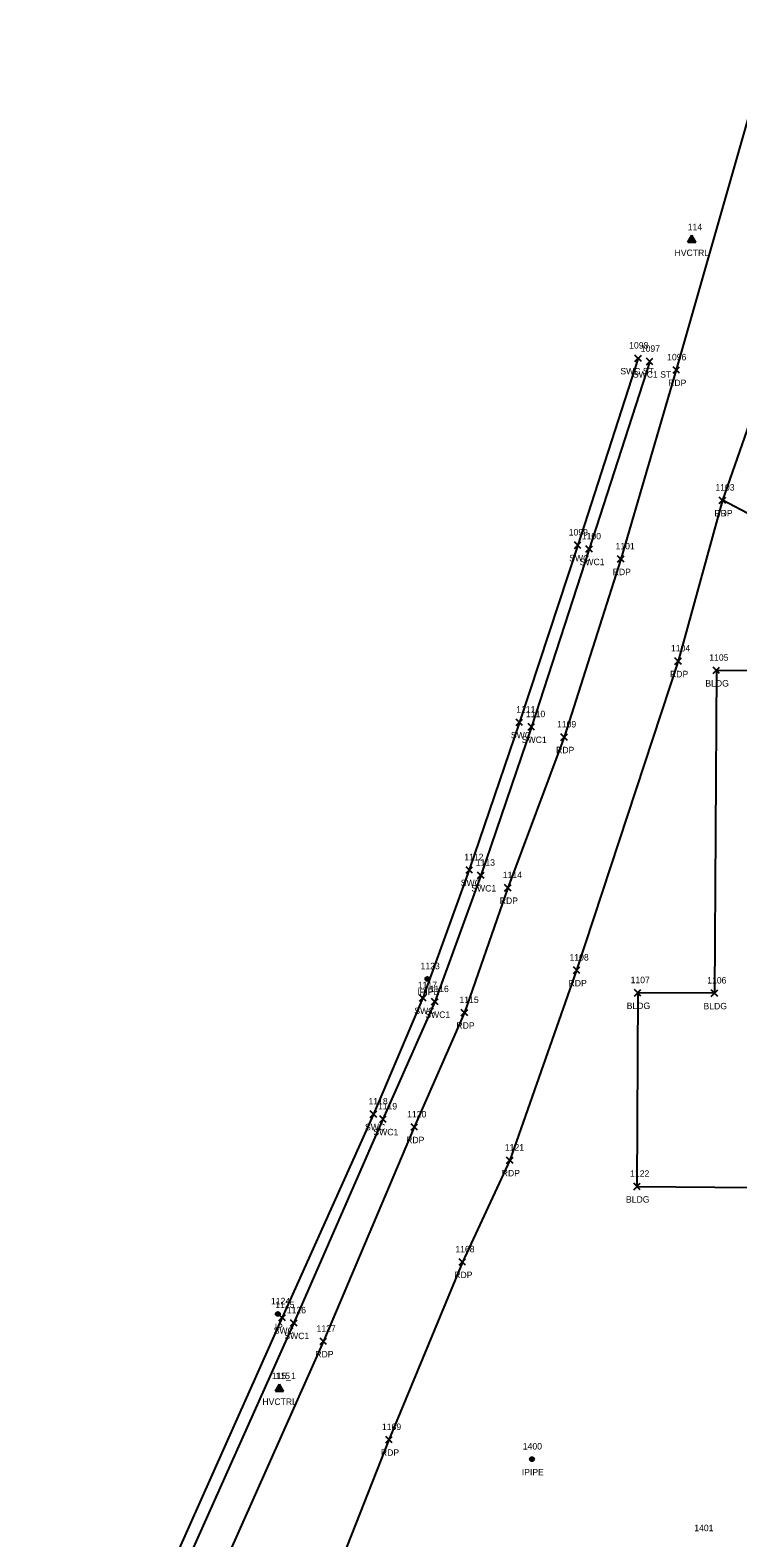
# Model space of a CAD drawing. Extents: x 1767353 to 1772625, y 740790 to 747702.
# Drawn here: x 1770036.3 to 1770255.6, y 742669.5 to 743136.9 of the extents above; entities that cross this region are included whole.
import ezdxf

# ---------------------------------------------------------------- set-up
doc = ezdxf.new("R2010")
doc.units = 0
for name, color, linetype in [('C_A', 7, 'Continuous'), ('C_I', 7, 'Continuous'), ('CPSM', 7, 'Continuous'), ('L_A', 7, 'Continuous'), ('L_I', 7, 'Continuous'), ('L_TIC', 7, 'Continuous'), ('LBC', 7, 'Continuous'), ('M_A', 7, 'Continuous'), ('M_I', 7, 'Continuous'), ('MPIP', 7, 'Continuous'), ('MPIR', 7, 'Continuous'), ('P_A', 7, 'Continuous'), ('P_I', 7, 'Continuous'), ('P_TIC', 7, 'Continuous'), ('PET', 7, 'Continuous'), ('R_A', 7, 'Continuous'), ('R_I', 7, 'Continuous'), ('R_TIC', 7, 'Continuous'), ('RDP', 7, 'Continuous'), ('RSW', 7, 'Continuous')]:
    doc.layers.add(name, color=color, linetype=linetype)

msp = doc.modelspace()

# ---------------------------------------------------------------- linework, layer by layer
at = {"layer": 'CPSM'}
for p, q in [((1770240.05, 743071.17), (1770241.3, 743073.33)), ((1770240.05, 743071.17), (1770241.3, 743073.33)), ((1770240.05, 743071.17), (1770241.3, 743073.33)), ((1770240.05, 743071.17), (1770241.3, 743073.33)), ((1770240.05, 743071.17), (1770241.3, 743073.33)), ((1770240.05, 743071.17), (1770241.3, 743073.33)), ((1770240.05, 743071.17), (1770241.3, 743073.33)), ((1770240.05, 743071.17), (1770241.3, 743071.89)), ((1770240.05, 743071.17), (1770241.3, 743071.89)), ((1770240.05, 743071.17), (1770241.3, 743071.89)), ((1770240.05, 743071.17), (1770241.3, 743071.89)), ((1770240.05, 743071.17), (1770241.3, 743071.89)), ((1770240.05, 743071.17), (1770241.3, 743071.89)), ((1770240.05, 743071.17), (1770241.3, 743071.89)), ((1770242.55, 743071.17), (1770241.3, 743073.33)), ((1770241.3, 743071.89), (1770241.3, 743073.33)), ((1770242.55, 743071.17), (1770241.3, 743073.33)), ((1770241.3, 743071.89), (1770241.3, 743073.33)), ((1770242.55, 743071.17), (1770241.3, 743073.33)), ((1770241.3, 743071.89), (1770241.3, 743073.33)), ((1770242.55, 743071.17), (1770241.3, 743073.33)), ((1770241.3, 743071.89), (1770241.3, 743073.33)), ((1770242.55, 743071.17), (1770241.3, 743073.33)), ((1770241.3, 743071.89), (1770241.3, 743073.33)), ((1770242.55, 743071.17), (1770241.3, 743073.33)), ((1770241.3, 743071.89), (1770241.3, 743073.33)), ((1770242.55, 743071.17), (1770241.3, 743073.33)), ((1770241.3, 743071.89), (1770241.3, 743073.33)), ((1770241.3, 743071.89), (1770241.3, 743071.89)), ((1770241.3, 743071.89), (1770242.55, 743071.17)), ((1770241.3, 743071.89), (1770241.3, 743071.89)), ((1770241.3, 743071.89), (1770242.55, 743071.17)), ((1770241.3, 743071.89), (1770241.3, 743071.89)), ((1770241.3, 743071.89), (1770242.55, 743071.17)), ((1770241.3, 743071.89), (1770241.3, 743071.89)), ((1770241.3, 743071.89), (1770242.55, 743071.17)), ((1770241.3, 743071.89), (1770241.3, 743071.89)), ((1770241.3, 743071.89), (1770242.55, 743071.17)), ((1770241.3, 743071.89), (1770241.3, 743071.89)), ((1770241.3, 743071.89), (1770242.55, 743071.17)), ((1770241.3, 743071.89), (1770241.3, 743071.89)), ((1770241.3, 743071.89), (1770242.55, 743071.17)), ((1770240.05, 743071.17), (1770242.55, 743071.17)), ((1770240.05, 743071.17), (1770242.55, 743071.17)), ((1770240.05, 743071.17), (1770242.55, 743071.17)), ((1770240.05, 743071.17), (1770242.55, 743071.17)), ((1770240.05, 743071.17), (1770242.55, 743071.17)), ((1770240.05, 743071.17), (1770242.55, 743071.17)), ((1770240.05, 743071.17), (1770242.55, 743071.17)), ((1770112.3, 742715), (1770113.55, 742717.17)), ((1770112.3, 742715), (1770113.55, 742717.17)), ((1770112.3, 742715), (1770113.55, 742717.17)), ((1770112.3, 742715), (1770113.55, 742717.17)), ((1770112.3, 742715), (1770113.55, 742717.17)), ((1770112.3, 742715), (1770113.55, 742717.17)), ((1770112.3, 742715), (1770113.55, 742717.17)), ((1770114.8, 742715), (1770113.55, 742717.17)), ((1770113.55, 742715.72), (1770113.55, 742717.17)), ((1770114.8, 742715), (1770113.55, 742717.17)), ((1770113.55, 742715.72), (1770113.55, 742717.17)), ((1770114.8, 742715), (1770113.55, 742717.17)), ((1770113.55, 742715.72), (1770113.55, 742717.17)), ((1770114.8, 742715), (1770113.55, 742717.17)), ((1770113.55, 742715.72), (1770113.55, 742717.17)), ((1770114.8, 742715), (1770113.55, 742717.17)), ((1770113.55, 742715.72), (1770113.55, 742717.17)), ((1770114.8, 742715), (1770113.55, 742717.17)), ((1770113.55, 742715.72), (1770113.55, 742717.17)), ((1770114.8, 742715), (1770113.55, 742717.17)), ((1770113.55, 742715.72), (1770113.55, 742717.17)), ((1770112.3, 742715), (1770113.55, 742715.72)), ((1770112.3, 742715), (1770113.55, 742715.72)), ((1770112.3, 742715), (1770113.55, 742715.72)), ((1770112.3, 742715), (1770113.55, 742715.72)), ((1770112.3, 742715), (1770113.55, 742715.72)), ((1770112.3, 742715), (1770113.55, 742715.72)), ((1770112.3, 742715), (1770113.55, 742715.72)), ((1770112.3, 742715), (1770114.8, 742715)), ((1770112.3, 742715), (1770114.8, 742715)), ((1770112.3, 742715), (1770114.8, 742715)), ((1770112.3, 742715), (1770114.8, 742715)), ((1770112.3, 742715), (1770114.8, 742715)), ((1770112.3, 742715), (1770114.8, 742715)), ((1770112.3, 742715), (1770114.8, 742715)), ((1770113.55, 742715.72), (1770113.55, 742715.72)), ((1770113.55, 742715.72), (1770114.8, 742715)), ((1770113.55, 742715.72), (1770113.55, 742715.72)), ((1770113.55, 742715.72), (1770114.8, 742715)), ((1770113.55, 742715.72), (1770113.55, 742715.72)), ((1770113.55, 742715.72), (1770114.8, 742715)), ((1770113.55, 742715.72), (1770113.55, 742715.72)), ((1770113.55, 742715.72), (1770114.8, 742715)), ((1770113.55, 742715.72), (1770113.55, 742715.72)), ((1770113.55, 742715.72), (1770114.8, 742715)), ((1770113.55, 742715.72), (1770113.55, 742715.72)), ((1770113.55, 742715.72), (1770114.8, 742715)), ((1770113.55, 742715.72), (1770113.55, 742715.72)), ((1770113.55, 742715.72), (1770114.8, 742715))]:
    msp.add_line(p, q, dxfattribs=at)
at = {"layer": 'L_TIC'}
for points in [[(1770247.94, 742937.42), (1770249.94, 742939.42)], [(1770249.94, 742937.42), (1770247.94, 742939.42)], [(1770223.56, 742837.46), (1770225.56, 742839.46)], [(1770225.56, 742837.46), (1770223.56, 742839.46)], [(1770247.37, 742837.36), (1770249.37, 742839.36)], [(1770249.37, 742837.36), (1770247.37, 742839.36)], [(1770223.34, 742777.43), (1770225.34, 742779.43)], [(1770225.34, 742777.43), (1770223.34, 742779.43)]]:
    msp.add_lwpolyline(points, dxfattribs=at)
at = {"layer": 'LBC'}
for points in [[(1770248.94, 742938.42), (1770248.37, 742838.36), (1770224.56, 742838.46), (1770224.34, 742778.43)], [(1770309.49, 742938.27), (1770248.94, 742938.42)], [(1770224.34, 742778.43), (1770308.79, 742777.69)]]:
    msp.add_lwpolyline(points, dxfattribs=at)
at = {"layer": 'MPIP'}
for centre, radius in [((1770159.38, 742842.79), 0.625), ((1770159.38, 742842.79), 0.0833), ((1770191.8, 742693.89), 0.625), ((1770191.8, 742693.89), 0.0833)]:
    msp.add_circle(centre, radius, dxfattribs=at)
at = {"layer": 'MPIR'}
for radius in [0.625, 0.0833]:
    msp.add_circle((1770113.02, 742738.91), radius, dxfattribs=at)
at = {"layer": 'P_TIC'}
for points in [[(1770235.51, 743030.56), (1770237.51, 743032.56)], [(1770237.51, 743030.56), (1770235.51, 743032.56)], [(1770249.85, 742990.18), (1770251.85, 742992.18)], [(1770251.85, 742990.18), (1770249.85, 742992.18)], [(1770218.34, 742971.95), (1770220.34, 742973.95)], [(1770220.34, 742971.95), (1770218.34, 742973.95)], [(1770236.09, 742940.3), (1770238.09, 742942.3)], [(1770238.09, 742940.3), (1770236.09, 742942.3)], [(1770200.78, 742916.74), (1770202.78, 742918.74)], [(1770202.78, 742916.74), (1770200.78, 742918.74)], [(1770183.32, 742870.03), (1770185.32, 742872.03)], [(1770185.32, 742870.03), (1770183.32, 742872.03)], [(1770204.64, 742844.48), (1770206.64, 742846.48)], [(1770206.64, 742844.48), (1770204.64, 742846.48)], [(1770169.89, 742831.33), (1770171.89, 742833.33)], [(1770171.89, 742831.33), (1770169.89, 742833.33)], [(1770154.31, 742795.84), (1770156.31, 742797.84)], [(1770156.31, 742795.84), (1770154.31, 742797.84)], [(1770183.95, 742785.57), (1770185.95, 742787.57)], [(1770185.95, 742785.57), (1770183.95, 742787.57)], [(1770169.21, 742754.02), (1770171.21, 742756.02)], [(1770171.21, 742754.02), (1770169.21, 742756.02)], [(1770126.15, 742729.43), (1770128.15, 742731.43)], [(1770128.15, 742729.43), (1770126.15, 742731.43)], [(1770146.48, 742698.94), (1770148.48, 742700.94)], [(1770148.48, 742698.94), (1770146.48, 742700.94)]]:
    msp.add_lwpolyline(points, dxfattribs=at)
at = {"layer": 'PET'}
for points in [[(1770287.36, 743218.01), (1770265.05, 743131.43), (1770236.51, 743031.56), (1770219.34, 742972.95), (1770201.78, 742917.74), (1770184.32, 742871.03), (1770170.89, 742832.33), (1770155.31, 742796.84), (1770127.15, 742730.43), (1770071.7, 742605.94), (1770068.18, 742600.07), (1770059.84, 742596.32), (1770058.18, 742592.27), (1770056.9, 742590.58), (1770055.34, 742589.72), (1770052.72, 742590.21), (1770049.12, 742591.83), (1770036.26, 742597.45)], [(1770318.5, 743207.69), (1770296.17, 743121.09), (1770250.85, 742991.18), (1770237.09, 742941.3), (1770205.64, 742845.48), (1770184.95, 742786.57), (1770170.21, 742755.02), (1770147.48, 742699.94), (1770126.77, 742647.43)]]:
    msp.add_lwpolyline(points, dxfattribs=at)
at = {"layer": 'R_TIC'}
for points in [[(1770223.69, 743034.2), (1770225.69, 743036.2)], [(1770225.69, 743034.2), (1770223.69, 743036.2)], [(1770227.29, 743033.19), (1770229.29, 743035.19)], [(1770229.29, 743033.19), (1770227.29, 743035.19)], [(1770249.85, 742990.18), (1770251.85, 742992.18)], [(1770251.85, 742990.18), (1770249.85, 742992.18)], [(1770204.97, 742976.24), (1770206.97, 742978.24)], [(1770206.97, 742976.24), (1770204.97, 742978.24)], [(1770208.52, 742975.05), (1770210.52, 742977.05)], [(1770210.52, 742975.05), (1770208.52, 742977.05)], [(1770186.9, 742921.34), (1770188.9, 742923.34)], [(1770188.9, 742921.34), (1770186.9, 742923.34)], [(1770190.6, 742919.92), (1770192.6, 742921.92)], [(1770192.6, 742919.92), (1770190.6, 742921.92)], [(1770171.36, 742875.56), (1770173.36, 742877.56)], [(1770173.36, 742875.56), (1770171.36, 742877.56)], [(1770174.94, 742873.88), (1770176.94, 742875.88)], [(1770176.94, 742873.88), (1770174.94, 742875.88)], [(1770156.95, 742835.89), (1770158.95, 742837.89)], [(1770158.95, 742835.89), (1770156.95, 742837.89)], [(1770160.68, 742834.7), (1770162.68, 742836.7)], [(1770162.68, 742834.7), (1770160.68, 742836.7)], [(1770141.69, 742799.86), (1770143.69, 742801.86)], [(1770143.69, 742799.86), (1770141.69, 742801.86)], [(1770144.6, 742798.3), (1770146.6, 742800.3)], [(1770146.6, 742798.3), (1770144.6, 742800.3)], [(1770113.37, 742736.77), (1770115.37, 742738.77)], [(1770115.37, 742736.77), (1770113.37, 742738.77)], [(1770116.99, 742735.11), (1770118.99, 742737.11)], [(1770118.99, 742735.11), (1770116.99, 742737.11)]]:
    msp.add_lwpolyline(points, dxfattribs=at)
at = {"layer": 'RDP'}
msp.add_lwpolyline([(1770358.02, 742818.47), (1770383, 742815.07), (1770381.79, 742805.76), (1770402.35, 742803.35), (1770416, 742845.87), (1770417.24, 742925.38), (1770417.05, 742964.46), (1770339.87, 742963.82), (1770324.43, 742957.55), (1770311.28, 742959.37), (1770250.85, 742991.18)], dxfattribs=at)
at = {"layer": 'RSW'}
for points in [[(1770224.69, 743035.2), (1770205.97, 742977.24), (1770187.9, 742922.34), (1770172.36, 742876.56), (1770157.95, 742836.89), (1770142.69, 742800.86), (1770114.37, 742737.77), (1770052.67, 742599.45), (1770040.21, 742604.87)], [(1770228.29, 743034.19), (1770209.52, 742976.05), (1770191.6, 742920.92), (1770175.94, 742874.88), (1770161.68, 742835.7), (1770145.6, 742799.3), (1770117.99, 742736.11), (1770056.07, 742597.76), (1770059.84, 742596.32)]]:
    msp.add_lwpolyline(points, dxfattribs=at)

# ---------------------------------------------------------------- texts
at = {"layer": 'C_A'}
for p in [(1770235.99, 743066.89), (1770235.99, 743066.89), (1770235.99, 743066.89), (1770235.99, 743066.89), (1770235.99, 743066.89), (1770235.99, 743066.89), (1770235.99, 743066.89), (1770108.24, 742710.72), (1770108.24, 742710.72), (1770108.24, 742710.72), (1770108.24, 742710.72), (1770108.24, 742710.72), (1770108.24, 742710.72), (1770108.24, 742710.72)]:
    msp.add_text('HVCTRL', height=2, dxfattribs=at).set_placement(p)
at = {"layer": 'C_I'}
for s, p in [('114', (1770240.07, 743074.89)), ('114', (1770240.07, 743074.89)), ('114', (1770240.07, 743074.89)), ('114', (1770240.07, 743074.89)), ('114', (1770240.07, 743074.89)), ('114', (1770240.07, 743074.89)), ('114', (1770240.07, 743074.89)), ('115_1', (1770111.17, 742718.72)), ('115', (1770112.32, 742718.72)), ('115', (1770112.32, 742718.72)), ('115', (1770112.32, 742718.72)), ('115', (1770112.32, 742718.72)), ('115', (1770112.32, 742718.72)), ('115', (1770112.32, 742718.72))]:
    msp.add_text(s, height=2, dxfattribs=at).set_placement(p)
at = {"layer": 'L_A'}
for p in [(1770245.53, 742933.42), (1770221.15, 742833.46), (1770244.96, 742833.36), (1770220.93, 742773.43)]:
    msp.add_text('BLDG', height=2, dxfattribs=at).set_placement(p)
at = {"layer": 'L_I'}
for s, p in [('1105', (1770246.74, 742941.42)), ('1107', (1770222.36, 742841.46)), ('1106', (1770246.11, 742841.36)), ('1122', (1770222.21, 742781.43))]:
    msp.add_text(s, height=2, dxfattribs=at).set_placement(p)
at = {"layer": 'M_A'}
for s, p in [('IPIPE', (1770156.22, 742837.79)), ('IP', (1770112.07, 742733.91)), ('IPIPE', (1770188.64, 742688.89))]:
    msp.add_text(s, height=2, dxfattribs=at).set_placement(p)
at = {"layer": 'M_I'}
for s, p in [('1123', (1770157.26, 742845.79)), ('1124', (1770110.9, 742741.91)), ('1400', (1770188.95, 742696.89)), ('1401', (1770242.09, 742671.57))]:
    msp.add_text(s, height=2, dxfattribs=at).set_placement(p)
at = {"layer": 'P_A'}
for p in [(1770234, 743026.56), (1770248.33, 742986.18), (1770216.82, 742967.95), (1770234.58, 742936.3), (1770199.27, 742912.74), (1770181.81, 742866.03), (1770203.13, 742840.48), (1770168.38, 742827.33), (1770152.8, 742791.84), (1770182.43, 742781.57), (1770167.7, 742750.02), (1770124.64, 742725.43), (1770144.97, 742694.94)]:
    msp.add_text('RDP', height=2, dxfattribs=at).set_placement(p)
at = {"layer": 'P_I'}
for s, p in [('1096', (1770233.68, 743034.56)), ('1103', (1770248.64, 742994.18)), ('1101', (1770217.7, 742975.95)), ('1104', (1770234.88, 742944.3)), ('1109', (1770199.56, 742920.74)), ('1114', (1770182.76, 742874.03)), ('1108', (1770203.43, 742848.48)), ('1115', (1770169.33, 742835.33)), ('1120', (1770153.1, 742799.84)), ('1121', (1770183.39, 742789.57)), ('1168', (1770168.04, 742758.02)), ('1127', (1770125.03, 742733.43)), ('1169', (1770145.3, 742702.94))]:
    msp.add_text(s, height=2, dxfattribs=at).set_placement(p)
at = {"layer": 'R_A'}
for s, p in [('SWC ST', (1770219.19, 743030.2)), ('SWC1 ST', (1770223.07, 743029.19)), ('DRP', (1770248.33, 742986.18)), ('SWC', (1770203.33, 742972.24)), ('SWC1', (1770206.56, 742971.05)), ('SWC', (1770185.26, 742917.34)), ('SWC1', (1770188.64, 742915.92)), ('SWC', (1770169.72, 742871.56)), ('SWC1', (1770172.98, 742869.88)), ('SWC', (1770155.32, 742831.89)), ('SWC1', (1770158.72, 742830.7)), ('SWC', (1770140.05, 742795.86)), ('SWC1', (1770142.64, 742794.3)), ('SWC', (1770111.73, 742732.77)), ('SWC1', (1770115.03, 742731.11))]:
    msp.add_text(s, height=2, dxfattribs=at).set_placement(p)
at = {"layer": 'R_I'}
for s, p in [('1098', (1770221.92, 743038.2)), ('1097', (1770225.52, 743037.19)), ('1103', (1770248.64, 742994.18)), ('1099', (1770203.19, 742980.24)), ('1100', (1770207.23, 742979.05)), ('1111', (1770186.91, 742925.34)), ('1110', (1770189.95, 742923.92)), ('1112', (1770170.8, 742879.56)), ('1113', (1770174.38, 742877.88)), ('1117', (1770156.4, 742839.89)), ('1116', (1770160.06, 742838.7)), ('1118', (1770141.13, 742803.86)), ('1119', (1770144.04, 742802.3)), ('1125', (1770112.24, 742740.77)), ('1126', (1770115.81, 742739.11))]:
    msp.add_text(s, height=2, dxfattribs=at).set_placement(p)

doc.saveas('drawing.dxf')
